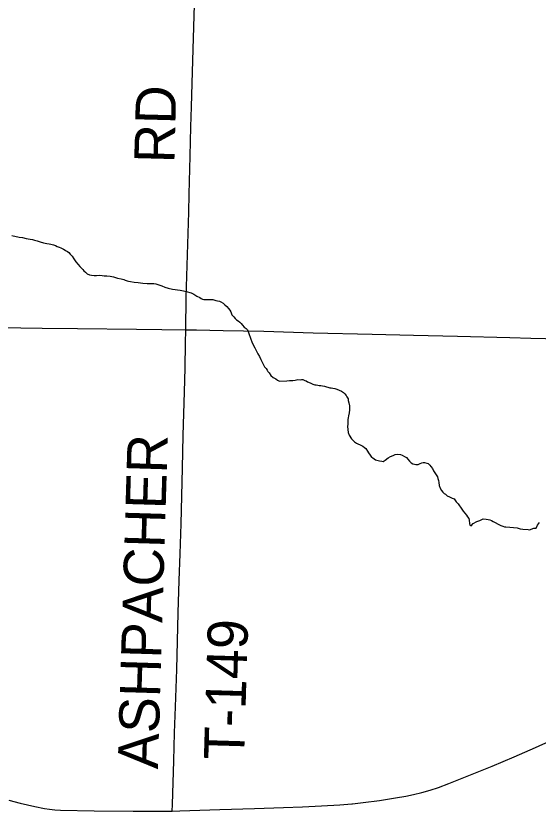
# Model space of a CAD drawing. Extents: x 0 to 34, y 0 to 22.
# Drawn here: x 24.635 to 25.373, y 18.784 to 19.908 of the extents above; entities that cross this region are included whole.
import ezdxf

# ---------------------------------------------------------------- set-up
doc = ezdxf.new("R2010")
doc.units = 0
for name, color, linetype in [('GM_X_Minor_River', 7, 'Continuous'), ('GM_X_Township_Road', 7, 'Continuous'), ('GM_X_Township_Road_Text', 7, 'Continuous')]:
    doc.layers.add(name, color=color, linetype=linetype)

msp = doc.modelspace()

# ---------------------------------------------------------------- linework, layer by layer
at = {"layer": 'GM_X_Minor_River'}
for points in [[(24.629, 19.598), (24.6392, 19.5955)], [(24.6392, 19.5955), (24.6441, 19.595), (24.649, 19.5937), (24.6547, 19.5928), (24.6581, 19.592), (24.6611, 19.5911), (24.6649, 19.5903), (24.669, 19.589), (24.6739, 19.5874), (24.6785, 19.5865), (24.6815, 19.5861), (24.6841, 19.5856), (24.6879, 19.5848), (24.6905, 19.5835), (24.6932, 19.5823), (24.6958, 19.5815), (24.6981, 19.5803), (24.6999, 19.5795), (24.7018, 19.5783), (24.7041, 19.5771), (24.7059, 19.5763), (24.7078, 19.5751), (24.7097, 19.5736), (24.7115, 19.5716), (24.7141, 19.5685), (24.7167, 19.5647), (24.7196, 19.5608), (24.7225, 19.5569), (24.7251, 19.5538), (24.7273, 19.5519), (24.7292, 19.5499), (24.7307, 19.548), (24.7329, 19.546), (24.7355, 19.5437), (24.7385, 19.5421), (24.7415, 19.5416), (24.7453, 19.5411), (24.7487, 19.5414), (24.7533, 19.5417), (24.7567, 19.5412), (24.7594, 19.5408), (24.7632, 19.5407), (24.7677, 19.5402), (24.7726, 19.5393), (24.7783, 19.5376), (24.7836, 19.5364), (24.787, 19.5355), (24.7892, 19.5347), (24.7919, 19.5339), (24.7937, 19.5335), (24.7968, 19.5326), (24.8017, 19.5317), (24.8077, 19.5312), (24.8142, 19.5303), (24.8202, 19.5301), (24.8256, 19.53), (24.8294, 19.5299), (24.8324, 19.5294), (24.8354, 19.5286), (24.8407, 19.5266), (24.8452, 19.5249), (24.8501, 19.5233), (24.8558, 19.522), (24.8667, 19.5206), (24.8716, 19.5197), (24.8754, 19.5189), (24.8826, 19.5168), (24.8863, 19.5148), (24.8904, 19.512), (24.8946, 19.5104), (24.8964, 19.5088), (24.8983, 19.508), (24.9002, 19.5076), (24.9025, 19.5072), (24.9048, 19.5075), (24.907, 19.5074), (24.9131, 19.5073), (24.9173, 19.506), (24.9195, 19.5056), (24.9222, 19.5048), (24.9241, 19.5043), (24.9278, 19.502), (24.93, 19.5), (24.933, 19.4976), (24.9352, 19.4949), (24.9371, 19.4922), (24.9385, 19.4899), (24.9399, 19.4857), (24.9425, 19.483), (24.9447, 19.4806), (24.9466, 19.4787), (24.9488, 19.4771), (24.9511, 19.4752), (24.9529, 19.4736), (24.9551, 19.4713), (24.9573, 19.4685), (24.9599, 19.4662), (24.9618, 19.4643), (24.9629, 19.462), (24.9643, 19.4577), (24.9657, 19.4543)], [(24.9657, 19.4543), (24.9668, 19.4512), (24.9682, 19.4474), (24.97, 19.4432), (24.9722, 19.4393), (24.9744, 19.4351), (24.9765, 19.4305), (24.9791, 19.4266), (24.9809, 19.4224), (24.983, 19.4181), (24.9859, 19.4124), (24.9885, 19.4097), (24.9896, 19.4077), (24.9907, 19.4058), (24.9926, 19.4035), (24.9951, 19.4), (24.9981, 19.3973), (25.0018, 19.3953), (25.0045, 19.3933), (25.0071, 19.3921), (25.0174, 19.3926), (25.0215, 19.3929), (25.0261, 19.3931), (25.0292, 19.3934), (25.0311, 19.3938), (25.0333, 19.3941), (25.0364, 19.394), (25.0383, 19.3943), (25.0402, 19.3943), (25.0428, 19.3931), (25.0447, 19.3923), (25.0469, 19.3911), (25.0507, 19.3895), (25.0545, 19.3879), (25.0571, 19.387), (25.059, 19.3866), (25.0616, 19.3862), (25.0635, 19.3857), (25.0654, 19.3857), (25.0681, 19.3852), (25.0707, 19.3848), (25.0734, 19.384), (25.0756, 19.3835), (25.0783, 19.3827), (25.0802, 19.3826), (25.0828, 19.3822), (25.0854, 19.3814), (25.0881, 19.3805), (25.0915, 19.3793), (25.0948, 19.3777), (25.0978, 19.3757), (25.0997, 19.3742), (25.1012, 19.3719), (25.1026, 19.3699), (25.1041, 19.3668), (25.1044, 19.3646), (25.1054, 19.3611), (25.1061, 19.3573), (25.106, 19.3516), (25.1055, 19.3471), (25.1046, 19.3429), (25.1042, 19.3399), (25.1037, 19.3376), (25.1037, 19.335), (25.1036, 19.3312), (25.1035, 19.3277), (25.1044, 19.3194), (25.1058, 19.3155), (25.1091, 19.3105), (25.1132, 19.3062), (25.1162, 19.3043), (25.1181, 19.3035), (25.1211, 19.3019), (25.1229, 19.301), (25.1252, 19.3002), (25.1274, 19.2983), (25.1293, 19.2967), (25.1315, 19.2932), (25.1329, 19.2905), (25.1355, 19.2874), (25.1373, 19.2847), (25.1392, 19.2835), (25.1429, 19.2808), (25.1448, 19.2804), (25.1486, 19.2795), (25.1516, 19.2787), (25.1535, 19.2786), (25.1566, 19.2801), (25.1609, 19.2834), (25.1643, 19.2856), (25.1678, 19.287), (25.1708, 19.2881), (25.1739, 19.2887), (25.1781, 19.2883), (25.1807, 19.2874), (25.1837, 19.2855), (25.1867, 19.2839), (25.1885, 19.2815), (25.1907, 19.2788), (25.1933, 19.2765), (25.1956, 19.2753)], [(25.1956, 19.2753), (25.1982, 19.2745), (25.2001, 19.274), (25.2032, 19.2743), (25.2059, 19.2758), (25.2082, 19.2765), (25.2101, 19.2768), (25.212, 19.2768), (25.2154, 19.2759), (25.2173, 19.2755), (25.2199, 19.2731), (25.2213, 19.2712), (25.2232, 19.2685), (25.225, 19.2654), (25.2268, 19.2623), (25.2286, 19.2596), (25.2305, 19.2566), (25.2312, 19.2546), (25.2318, 19.2516), (25.2322, 19.2489), (25.2328, 19.2443), (25.2342, 19.2405), (25.2361, 19.2374), (25.2379, 19.2351), (25.2401, 19.2331), (25.242, 19.232), (25.2442, 19.23), (25.2476, 19.2284), (25.2513, 19.2264), (25.254, 19.2256), (25.2569, 19.2213), (25.2595, 19.2186), (25.2617, 19.2159), (25.2632, 19.2139), (25.2668, 19.2082), (25.2691, 19.2054), (25.2713, 19.2027), (25.2731, 19.2), (25.2746, 19.1977), (25.2753, 19.1954), (25.2759, 19.1908), (25.2762, 19.1882), (25.2781, 19.1877), (25.2808, 19.1907), (25.2859, 19.1936), (25.2901, 19.195), (25.292, 19.1961), (25.2951, 19.1972), (25.2992, 19.1971), (25.3019, 19.1966), (25.3045, 19.1958), (25.3068, 19.195), (25.309, 19.1938), (25.312, 19.1922), (25.3161, 19.1898), (25.3199, 19.1878), (25.3229, 19.187), (25.3252, 19.1862), (25.3271, 19.1861), (25.3328, 19.1856), (25.3377, 19.1851), (25.343, 19.1846), (25.3475, 19.1833), (25.3513, 19.1829), (25.3585, 19.1823), (25.3604, 19.1819), (25.3665, 19.184), (25.3699, 19.1843), (25.3719, 19.1884), (25.3747, 19.1921)]]:
    msp.add_lwpolyline(points, dxfattribs=at)
at = {"layer": 'GM_X_Township_Road'}
for points in [[(24.8748, 19.4645), (24.8755, 19.5104), (24.8758, 19.5253), (24.8789, 19.631), (24.8796, 19.6564), (24.881, 19.7099), (24.8821, 19.7515), (24.8829, 19.7795), (24.8844, 19.8292), (24.888, 19.9566), (24.8895, 20.0115)], [(24.2089, 19.4738), (24.2517, 19.4733), (24.3387, 19.4721), (24.3723, 19.4716), (24.4326, 19.4708), (24.478, 19.4699), (24.5812, 19.4685), (24.6719, 19.4671), (24.7216, 19.4666), (24.8049, 19.4656), (24.841, 19.4651), (24.8748, 19.4645)], [(24.8555, 18.7843), (24.8558, 18.7937), (24.8579, 18.8553), (24.859, 18.8951), (24.8603, 18.9317), (24.8619, 18.9846), (24.8639, 19.0647), (24.8655, 19.1101), (24.8668, 19.148), (24.8684, 19.1903), (24.8699, 19.2692), (24.8711, 19.3152), (24.8728, 19.3767), (24.8737, 19.4103), (24.8745, 19.4457), (24.8748, 19.4645)], [(24.8748, 19.4645), (24.8901, 19.4643), (24.9274, 19.4638), (24.9852, 19.4624), (25.0547, 19.4604), (25.138, 19.4586), (25.1964, 19.4572), (25.2586, 19.4557), (25.3325, 19.4536), (25.3623, 19.4529), (25.445, 19.4507), (25.5742, 19.4477), (25.6743, 19.4453), (25.7141, 19.4446), (25.7713, 19.4431), (25.8216, 19.4419), (25.8479, 19.4412)], [(25.1096, 18.7944), (25.1106, 18.7945), (25.1255, 18.7964), (25.1483, 18.7994), (25.171, 18.8028), (25.1858, 18.8053), (25.1968, 18.8075), (25.2083, 18.8104), (25.2203, 18.8138), (25.2321, 18.8177), (25.2467, 18.8231), (25.3078, 18.8478), (25.3388, 18.8608), (25.3689, 18.8742), (25.4085, 18.8922), (25.439, 18.9063), (25.466, 18.9191), (25.4947, 18.9331)], [(24.6246, 18.7995), (24.6409, 18.7955), (24.6615, 18.7908), (24.675, 18.7881), (24.6824, 18.787), (24.6898, 18.7862), (24.6979, 18.7856), (24.7452, 18.7848), (24.8006, 18.7843), (24.8354, 18.7842), (24.8555, 18.7843)], [(24.8555, 18.7843), (24.8665, 18.7845), (24.923, 18.7863), (24.9721, 18.7878), (25.0131, 18.7894), (25.0398, 18.7904), (25.0665, 18.7917), (25.0926, 18.7931), (25.1096, 18.7944)]]:
    msp.add_lwpolyline(points, dxfattribs=at)

# ---------------------------------------------------------------- texts
at = {"layer": 'GM_X_Township_Road_Text'}
for s, rotation, p in [('RD', 88.5178, (24.8586, 19.6996)), ('ASHPACHER', 88.2851, (24.8353, 18.8433)), ('T-149', 88.3145, (24.9571, 18.8562))]:
    msp.add_text(s, height=0.05682, rotation=rotation, dxfattribs=at).set_placement(p)

doc.saveas('drawing.dxf')
